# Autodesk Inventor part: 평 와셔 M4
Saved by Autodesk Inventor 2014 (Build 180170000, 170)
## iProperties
Created: 2026-04
Part Number: 평 와셔 M4
Material: 일반
Document SubType Name: Modeling
Designer: dg
Density: 1 g/cm^3
Appearance: 기본값
Author: dg
Author: jhkim
Description: 평면 와셔
Creation Date: 2026-03-26
Sending System: Autodesk Inventor 2026
Preprocessor: ST-DEVELOPER v20.1
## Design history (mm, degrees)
node "평 와셔 M41"
body "Solid1"
node "기준1"
